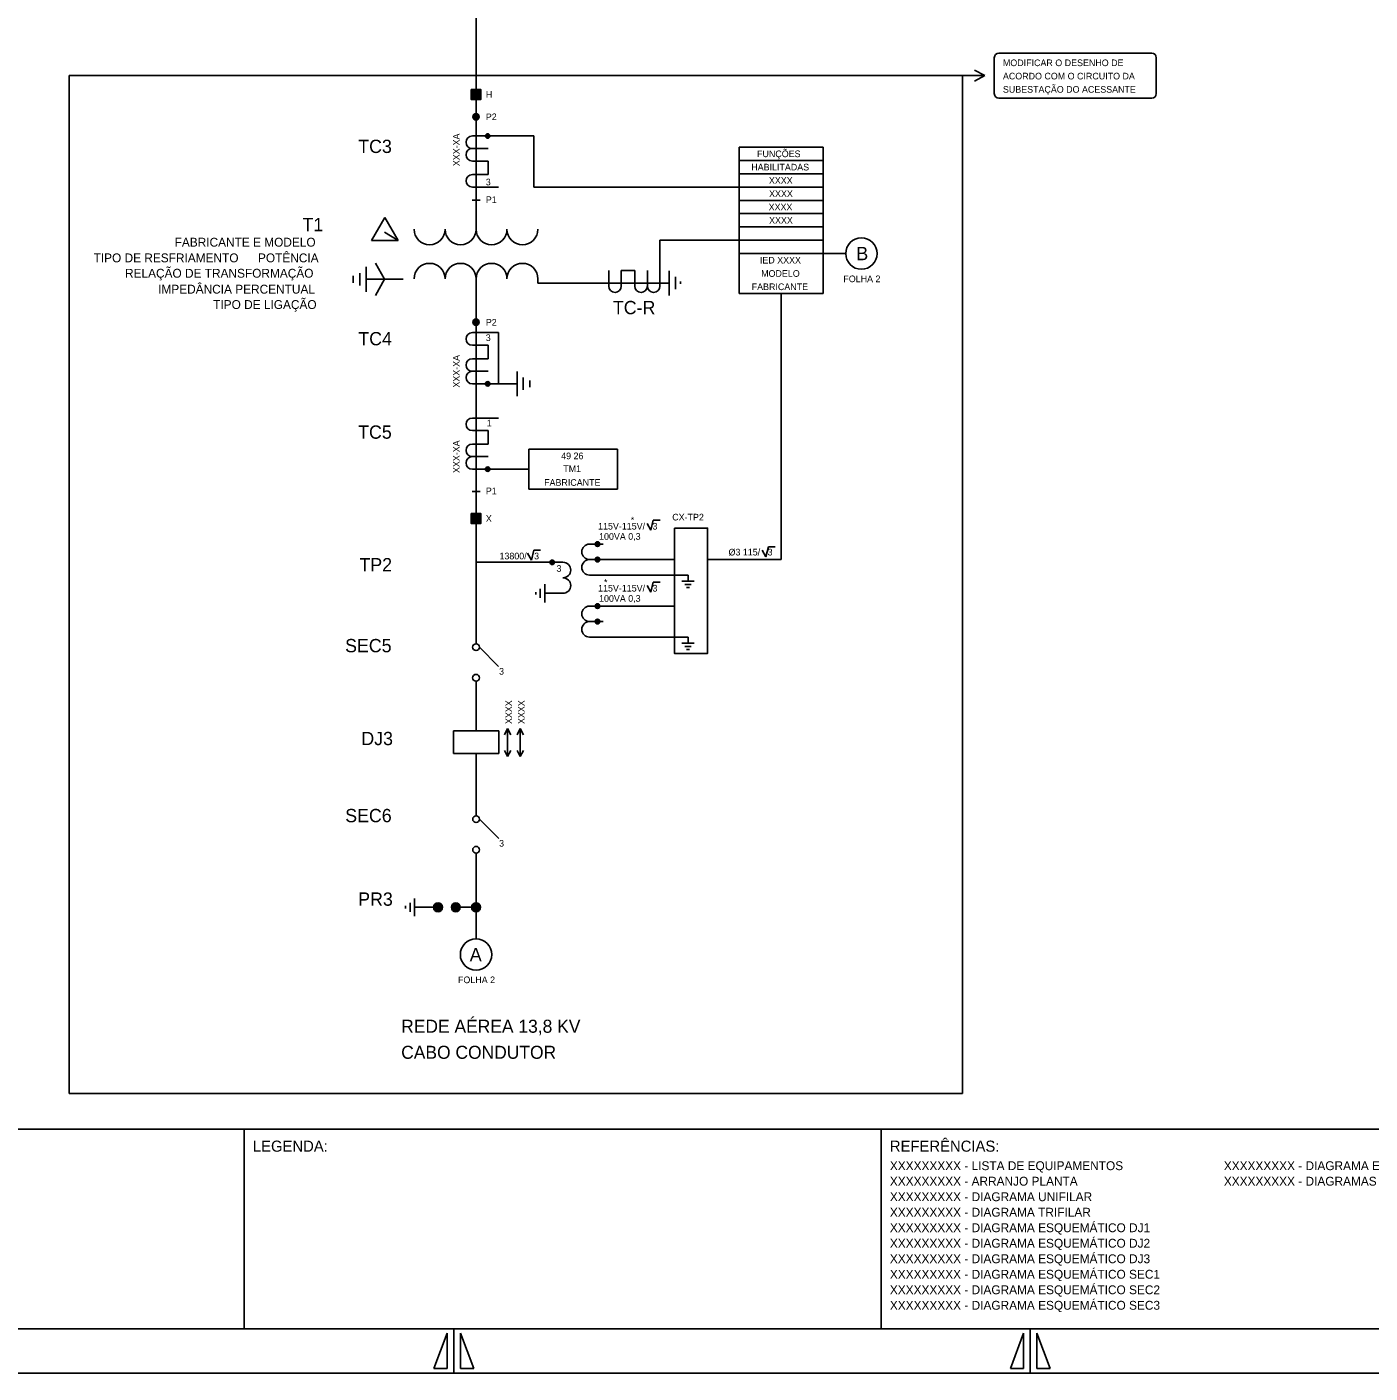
# Model space of a CAD drawing. Extents: x 501 to 1404, y 358 to 952.
# Drawn here: x 807.3 to 1110.2, y 358 to 661.7 of the extents above; entities that cross this region are included whole.
import ezdxf

# ---------------------------------------------------------------- set-up
doc = ezdxf.new("R2010")
doc.units = 0
doc.layers.add('New Level (0)', color=7, linetype='Continuous')

# ---------------------------------------------------------------- blocks, each defined once
blk = doc.blocks.new('_U3')
for p, q in [((-1.47, 0.42), (-0.62, -1.12)), ((-0.62, -1.12), (-0.07, 1.12)), ((-0.07, 1.12), (1.47, 1.12))]:
    blk.add_line(p, q)

msp = doc.modelspace()

# ---------------------------------------------------------------- linework, layer by layer
for p, q in [((908.57, 654.53), (908.57, 712.81)), ((908.57, 615.64), (908.57, 654.53)), ((907.45, 645.43), (909.61, 647.58)), ((907.45, 645.61), (909.43, 647.58)), ((907.45, 645.78), (909.25, 647.58)), ((907.45, 645.96), (909.08, 647.58)), ((907.45, 646.14), (908.9, 647.58)), ((907.45, 646.31), (908.72, 647.58)), ((907.45, 646.49), (908.54, 647.58)), ((907.45, 646.67), (908.37, 647.58)), ((907.45, 646.84), (908.19, 647.58)), ((907.45, 647.02), (908.01, 647.58)), ((907.45, 647.2), (907.84, 647.58)), ((907.45, 647.37), (907.66, 647.58)), ((907.45, 647.55), (907.48, 647.58)), ((907.57, 645.37), (909.66, 647.46)), ((907.75, 645.37), (909.66, 647.29)), ((907.92, 645.37), (909.66, 647.11)), ((908.1, 645.37), (909.66, 646.93)), ((908.28, 645.37), (909.66, 646.76)), ((908.46, 645.37), (909.66, 646.58)), ((908.63, 645.37), (909.66, 646.4)), ((908.81, 645.37), (909.66, 646.23)), ((908.99, 645.37), (909.66, 646.05)), ((909.16, 645.37), (909.66, 645.87)), ((909.34, 645.37), (909.66, 645.7)), ((909.52, 645.37), (909.66, 645.52)), ((907.75, 637.12), (921.57, 637.12)), ((921.57, 625.58), (921.57, 637.12)), ((907.75, 634.29), (911.29, 634.29)), ((967.89, 634.58), (967.89, 601.58)), ((986.87, 634.58), (967.89, 634.58)), ((986.87, 634.58), (986.87, 601.58)), ((907.75, 631.46), (911.29, 631.46)), ((911.29, 628.41), (911.29, 631.46)), ((986.87, 631.58), (967.89, 631.58)), ((907.75, 628.41), (911.29, 628.41)), ((986.87, 628.58), (967.89, 628.58)), ((907.75, 625.58), (913.62, 625.58)), ((921.57, 625.58), (968.49, 625.58)), ((986.87, 625.58), (967.89, 625.58)), ((986.87, 622.58), (967.89, 622.58)), ((884.99, 613.5), (888.02, 618.74)), ((888.02, 618.74), (891.04, 613.5)), ((986.87, 619.58), (967.89, 619.58)), ((891.04, 613.5), (887.95, 615.38)), ((986.87, 616.58), (967.89, 616.58)), ((986.87, 616.58), (967.89, 616.58)), ((891.04, 613.5), (884.99, 613.5)), ((950.04, 603.23), (950.04, 613.58)), ((950.04, 613.58), (967.89, 613.58)), ((986.87, 613.58), (967.89, 613.58)), ((991.94, 610.58), (967.89, 610.58)), ((883.76, 601.97), (883.76, 607.56)), ((887.95, 604.77), (885.86, 608.4)), ((880.89, 603.99), (880.89, 605.55)), ((882.37, 606.16), (882.37, 603.37)), ((892.14, 604.77), (883.76, 604.77)), ((887.95, 604.77), (885.86, 601.14)), ((922.53, 604.88), (922.53, 603.92)), ((938.5, 603.23), (938.5, 606.76)), ((941.33, 606.76), (944.38, 606.76)), ((941.33, 603.23), (941.33, 606.76)), ((944.38, 603.23), (944.38, 606.76)), ((947.21, 603.23), (947.21, 606.76)), ((952.16, 606.71), (952.16, 601.13)), ((953.55, 602.52), (953.55, 605.32)), ((922.53, 603.92), (952.16, 603.92)), ((954.72, 604.26), (954.72, 603.73)), ((986.87, 601.58), (967.89, 601.58)), ((977.38, 541.52), (977.38, 601.58)), ((907.75, 592.73), (913.62, 592.73)), ((907.75, 589.9), (911.29, 589.9)), ((911.29, 589.9), (911.29, 586.85)), ((907.75, 586.85), (911.29, 586.85)), ((907.75, 584.02), (911.29, 584.02)), ((917.81, 578.39), (917.81, 583.98)), ((907.75, 581.19), (911.29, 581.19)), ((911.29, 581.19), (917.81, 581.19)), ((919.2, 582.58), (919.2, 579.79)), ((920.68, 580.41), (920.68, 581.97)), ((907.75, 573.47), (913.62, 573.47)), ((907.75, 570.64), (911.29, 570.64)), ((911.29, 570.64), (911.29, 567.58)), ((907.75, 567.58), (911.29, 567.58)), ((920.5, 566.42), (920.5, 557.42)), ((920.5, 566.42), (940.48, 566.42)), ((940.48, 566.42), (940.48, 557.42)), ((907.75, 564.75), (911.29, 564.75)), ((907.75, 561.92), (920.5, 561.92)), ((907.75, 561.92), (911.29, 561.92)), ((920.5, 557.42), (940.48, 557.42)), ((907.45, 549.75), (909.61, 551.9)), ((907.45, 549.92), (909.43, 551.9)), ((907.45, 550.1), (909.25, 551.9)), ((907.45, 550.28), (909.08, 551.9)), ((907.45, 550.45), (908.9, 551.9)), ((907.45, 550.63), (908.72, 551.9)), ((907.45, 550.81), (908.54, 551.9)), ((907.45, 550.99), (908.37, 551.9)), ((907.45, 551.16), (908.19, 551.9)), ((907.45, 551.34), (908.01, 551.9)), ((907.45, 551.52), (907.84, 551.9)), ((907.45, 551.69), (907.66, 551.9)), ((907.45, 551.87), (907.48, 551.9)), ((907.57, 549.69), (909.66, 551.78)), ((907.75, 549.69), (909.66, 551.61)), ((907.92, 549.69), (909.66, 551.43)), ((908.1, 549.69), (909.66, 551.25)), ((908.28, 549.69), (909.66, 551.07)), ((908.46, 549.69), (909.66, 550.9)), ((908.63, 549.69), (909.66, 550.72)), ((908.81, 549.69), (909.66, 550.54)), ((908.99, 549.69), (909.66, 550.37)), ((909.16, 549.69), (909.66, 550.19)), ((909.34, 549.69), (909.66, 550.01)), ((909.52, 549.69), (909.66, 549.84)), ((934.17, 545.02), (937.28, 545.02)), ((908.58, 540.91), (928.17, 540.91)), ((934.17, 541.52), (953.31, 541.52)), ((960.79, 541.52), (977.38, 541.52)), ((934.17, 538.02), (956.4, 538.02)), ((956.4, 538.02), (956.4, 536.62)), ((923.05, 532.88), (923.05, 534.93)), ((924.08, 535.95), (924.08, 531.86)), ((957.8, 536.62), (955, 536.62)), ((955.7, 535.92), (957.1, 535.92)), ((956.06, 535.22), (956.74, 535.22)), ((922.04, 534.15), (922.04, 533.61)), ((928.17, 533.91), (924.08, 533.91)), ((953.31, 531.03), (934.17, 531.03)), ((934.17, 527.53), (937.28, 527.53)), ((934.17, 524.03), (956.4, 524.03)), ((957.8, 522.63), (955, 522.63)), ((956.4, 524.03), (956.4, 522.63)), ((913.67, 517.42), (909.34, 521.76)), ((955.7, 521.93), (957.1, 521.93)), ((956.06, 521.23), (956.74, 521.23)), ((903.45, 497.76), (903.45, 502.88)), ((903.45, 502.88), (913.69, 502.88)), ((913.69, 502.88), (913.69, 497.76)), ((915.69, 503.42), (914.98, 502.01)), ((915.69, 497.05), (915.69, 503.42)), ((915.69, 503.42), (916.39, 502.01)), ((918.54, 503.42), (917.83, 502.01)), ((918.54, 497.05), (918.54, 503.42)), ((918.54, 503.42), (919.24, 502.01)), ((915.69, 497.05), (914.98, 498.47)), ((915.69, 497.05), (916.39, 498.47)), ((918.54, 497.05), (917.83, 498.47)), ((918.54, 497.05), (919.24, 498.47)), ((913.69, 497.76), (903.45, 497.76)), ((913.68, 478.61), (909.34, 482.95)), ((894.68, 461.06), (894.68, 465.06)), ((892.68, 463.36), (892.68, 462.76)), ((892.68, 463.06), (892.68, 463.06)), ((893.68, 464.06), (893.68, 462.06)), ((896, 463.06), (894.68, 463.06)), ((900, 463.06), (896, 463.06)), ((908.58, 463.06), (904, 463.06))]:
    msp.add_line(p, q)
for points in [[(907.45, 647.58), (909.66, 647.58), (909.66, 645.37), (907.45, 645.37)], [(907.45, 551.9), (909.66, 551.9), (909.66, 549.69), (907.45, 549.69)]]:
    msp.add_lwpolyline(points, close=True)
for centre, radius in [((908.56, 641.45), 0.729), ((908.57, 641.45), 0.511), ((908.57, 641.45), 0.288), ((911.2, 637.11), 0.511), ((911.2, 637.11), 0.288), ((908.56, 595.09), 0.729), ((908.57, 595.09), 0.511), ((908.57, 595.09), 0.288), ((911.2, 581.19), 0.511), ((911.2, 581.19), 0.288), ((911.2, 561.93), 0.511), ((911.2, 561.93), 0.288), ((935.97, 545.02), 0.511), ((935.97, 545.02), 0.288), ((925.73, 540.9), 0.511), ((925.73, 540.9), 0.288), ((935.97, 541.52), 0.511), ((935.97, 541.52), 0.288), ((935.97, 531.03), 0.511), ((935.97, 531.03), 0.288), ((935.97, 527.53), 0.511), ((935.97, 527.53), 0.288), ((908.57, 521.76), 0.768), ((908.57, 514.85), 0.768), ((908.58, 482.95), 0.768), ((908.58, 476.04), 0.768), ((900, 463.06), 1), ((900, 463.06), 0.75), ((900, 463.06), 0.5), ((900, 463.06), 0.25), ((904, 463.06), 1), ((904, 463.06), 0.75), ((904, 463.06), 0.5), ((904, 463.06), 0.25), ((908.58, 463.06), 1), ((908.58, 463.06), 0.75), ((908.58, 463.06), 0.5), ((908.58, 463.06), 0.25)]:
    msp.add_circle(centre, radius)
for centre, radius, start, end in [((907.75, 635.7), 1.42, 90, 270), ((907.75, 632.87), 1.42, 90, 270), ((907.75, 626.99), 1.42, 90, 270), ((898.09, 616.05), 3.49, 180, 0), ((905.08, 616.05), 3.49, 180, 0), ((912.06, 616.05), 3.49, 180, 0), ((919.04, 616.05), 3.49, 180, 0), ((898.09, 604.88), 3.49, 0, 180), ((905.08, 604.88), 3.49, 0, 180), ((912.06, 604.88), 3.49, 0, 180), ((919.04, 604.88), 3.49, 0, 180), ((939.92, 603.23), 1.42, 180, 0), ((945.8, 603.23), 1.42, 180, 0), ((948.63, 603.23), 1.42, 180, 0), ((907.75, 591.31), 1.42, 90, 270), ((907.75, 585.43), 1.42, 90, 270), ((907.75, 582.6), 1.42, 90, 270), ((907.75, 572.05), 1.42, 90, 270), ((907.75, 566.17), 1.42, 90, 270), ((907.75, 563.34), 1.42, 90, 270), ((934.17, 543.27), 1.75, 90, 270), ((928.17, 539.16), 1.75, 270, 90), ((934.17, 539.77), 1.75, 90, 270), ((928.17, 535.66), 1.75, 270, 90), ((934.17, 529.28), 1.75, 90, 270), ((934.17, 525.78), 1.75, 90, 270)]:
    msp.add_arc(centre, radius, start, end)
at = {"layer": 'New Level (0)'}
for p, q in [((1025.47, 646.67), (1025.47, 654.78)), ((1026.47, 655.78), (1033.82, 655.78)), ((1033.82, 655.78), (1061.01, 655.78)), ((1062.01, 654.78), (1062.01, 646.67)), ((1018.28, 650.72), (1023.31, 650.72)), ((1023.31, 650.72), (1021.02, 651.93)), ((1023.31, 650.72), (1021.02, 649.51)), ((1061.01, 645.67), (1026.47, 645.67)), ((907.68, 622.62), (909.47, 622.62)), ((908.57, 604.88), (908.57, 522.53)), ((913.62, 581.19), (913.62, 592.73)), ((907.68, 556.9), (909.47, 556.9)), ((908.57, 514.08), (908.57, 502.88)), ((908.57, 497.76), (908.57, 483.72)), ((908.57, 475.28), (908.57, 455.94)), ((572.58, 412.96), (1393.58, 412.96)), ((856.24, 412.96), (856.24, 367.96)), ((999.91, 412.96), (999.91, 367.96)), ((572.58, 367.96), (1393.58, 367.96)), ((572.58, 367.96), (1393.58, 367.96)), ((903.58, 367.96), (903.58, 357.96)), ((1033.58, 367.96), (1033.58, 357.96)), ((899.08, 358.96), (902.08, 366.96)), ((902.08, 366.96), (902.08, 358.96)), ((905.08, 366.96), (905.08, 358.96)), ((908.08, 358.96), (905.08, 366.96)), ((1029.08, 358.96), (1032.08, 366.96)), ((1032.08, 366.96), (1032.08, 358.96)), ((1035.08, 366.96), (1035.08, 358.96)), ((1038.08, 358.96), (1035.08, 366.96)), ((902.08, 358.96), (899.08, 358.96)), ((905.08, 358.96), (908.08, 358.96)), ((1032.08, 358.96), (1029.08, 358.96)), ((1035.08, 358.96), (1038.08, 358.96)), ((562.58, 357.96), (1403.58, 357.96)), ((562.58, 357.96), (1403.58, 357.96))]:
    msp.add_line(p, q, dxfattribs=at)
for points in [[(816.8, 650.72), (1018.28, 650.72), (1018.28, 421.07), (816.8, 421.07)], [(953.31, 548.62), (960.79, 548.62), (960.79, 520.33), (953.31, 520.33)]]:
    msp.add_lwpolyline(points, close=True, dxfattribs=at)
for centre in [(995.49, 610.58), (908.57, 452.4)]:
    msp.add_circle(centre, 3.54, dxfattribs=at)
for centre, start, end in [((1026.47, 654.78), 90, 180), ((1061.01, 654.78), 0, 90), ((1026.47, 646.67), 180, 270), ((1061.01, 646.67), 270, 0)]:
    msp.add_arc(centre, 1, start, end, dxfattribs=at)

# ---------------------------------------------------------------- block references
for p in [(948.6, 549.27), (974.58, 543.25), (921.67, 542.54), (948.6, 535.28)]:
    msp.add_blockref('_U3', p)

# ---------------------------------------------------------------- texts
for s, height, p in [('MODIFICAR O DESENHO DE ', 1.5, (1027.41, 652.87)), ('ACORDO COM O CIRCUITO DA ', 1.5, (1027.41, 649.87)), ('H', 1.5, (910.78, 645.73)), ('SUBESTAÇÃO DO ACESSANTE', 1.5, (1027.41, 646.87)), ('P2', 1.5, (910.78, 640.68)), ('TC3', 3, (882, 633.27)), ('FUNÇÕES ', 1.5, (971.95, 632.33)), ('HABILITADAS', 1.5, (970.65, 629.33)), ('3', 1.5, (910.77, 625.97)), ('XXXX', 1.5, (974.63, 626.33)), ('P1', 1.5, (910.78, 621.99)), ('XXXX', 1.5, (974.67, 623.33)), ('XXXX', 1.5, (974.57, 620.33)), ('T1', 3, (869.44, 615.61)), ('XXXX', 1.5, (974.67, 617.33)), ('FABRICANTE E MODELO', 2, (840.59, 612.14)), ('TIPO DE RESFRIAMENTO ', 2, (822.31, 608.6)), ('POTÊNCIA', 2, (859.39, 608.6)), ('B', 3, (994.35, 609.08)), ('RELAÇÃO DE TRANSFORMAÇÃO', 2, (829.4, 605.13)), ('IED XXXX', 1.5, (972.6, 608.33)), ('MODELO', 1.5, (972.88, 605.33)), ('FOLHA 2', 1.5, (991.42, 604.12)), ('IMPEDÂNCIA PERCENTUAL', 2, (836.87, 601.54)), ('FABRICANTE', 1.5, (970.75, 602.33)), ('TIPO DE LIGAÇÃO', 2, (849.28, 598.07)), ('TC-R', 3, (939.44, 596.89)), ('P2', 1.5, (910.78, 594.32)), ('TC4', 3, (882.02, 589.87)), ('3', 1.5, (910.77, 590.85)), ('TC5', 3, (881.98, 568.79)), ('1', 1.5, (910.99, 571.57)), ('49 26', 1.5, (927.77, 564.17)), ('TM1', 1.5, (928.25, 561.29)), ('FABRICANTE', 1.5, (923.93, 558.17)), ('P1', 1.5, (910.78, 556.27)), ('X', 1.5, (910.78, 550.05)), ('115V-115V/   3', 1.5, (936.1, 548.3)), ('*', 1.5, (943.46, 549.72)), ('CX-TP2', 1.5, (952.82, 550.35)), ('100VA 0,3', 1.5, (936.32, 545.99)), ('Ø3 115/   3', 1.5, (965.52, 542.45)), ('TP2', 3, (882.27, 538.87)), ('13800/   3', 1.5, (913.86, 541.57)), ('3', 1.5, (926.71, 538.76)), ('115V-115V/   3', 1.5, (936.1, 534.31)), ('*', 1.5, (937.43, 535.67)), ('100VA 0,3', 1.5, (936.32, 532)), ('SEC5', 3, (879.04, 520.61)), ('3', 1.5, (913.76, 515.56)), ('DJ3', 3, (882.7, 499.65)), ('SEC6', 3, (879.06, 482.26)), ('3', 1.5, (913.77, 476.75)), ('PR3', 3, (881.99, 463.41)), ('A', 3, (907.16, 450.9)), ('FOLHA 2', 1.5, (904.5, 445.94)), ('REDE AÉREA 13,8 KV', 2.94, (891.69, 434.75)), ('CABO CONDUTOR ', 2.94, (891.69, 428.87))]:
    msp.add_text(s, height=height).set_placement(p)
for s, p in [('XXX-XA', (904.88, 630.3)), ('XXX-XA', (904.88, 580.33)), ('XXX-XA', (904.88, 561.06)), ('XXXX', (916.69, 504.42)), ('XXXX', (919.54, 504.42))]:
    msp.add_text(s, height=1.5, rotation=90).set_placement(p)
for s, height, p in [('LEGENDA:', 2.5, (858.24, 407.91)), ('REFERÊNCIAS:', 2.5, (1001.91, 407.91)), ('XXXXXXXXX - LISTA DE EQUIPAMENTOS', 2, (1001.91, 403.75)), ('XXXXXXXXX - DIAGRAMA ESQUEMÁTICO SEC4', 2, (1077.23, 403.75)), ('XXXXXXXXX - ARRANJO PLANTA', 2, (1001.91, 400.25)), ('XXXXXXXXX - DIAGRAMAS LÓGICOS', 2, (1077.23, 400.25)), ('XXXXXXXXX - DIAGRAMA UNIFILAR', 2, (1001.91, 396.75)), ('XXXXXXXXX - DIAGRAMA TRIFILAR', 2, (1001.91, 393.25)), ('XXXXXXXXX - DIAGRAMA ESQUEMÁTICO DJ1', 2, (1001.91, 389.75)), ('XXXXXXXXX - DIAGRAMA ESQUEMÁTICO DJ2', 2, (1001.91, 386.25)), ('XXXXXXXXX - DIAGRAMA ESQUEMÁTICO DJ3', 2, (1001.91, 382.75)), ('XXXXXXXXX - DIAGRAMA ESQUEMÁTICO SEC1', 2, (1001.91, 379.25)), ('XXXXXXXXX - DIAGRAMA ESQUEMÁTICO SEC2', 2, (1001.91, 375.75)), ('XXXXXXXXX - DIAGRAMA ESQUEMÁTICO SEC3', 2, (1001.91, 372.25))]:
    msp.add_text(s, height=height, dxfattribs=at).set_placement(p)

doc.saveas('drawing.dxf')
